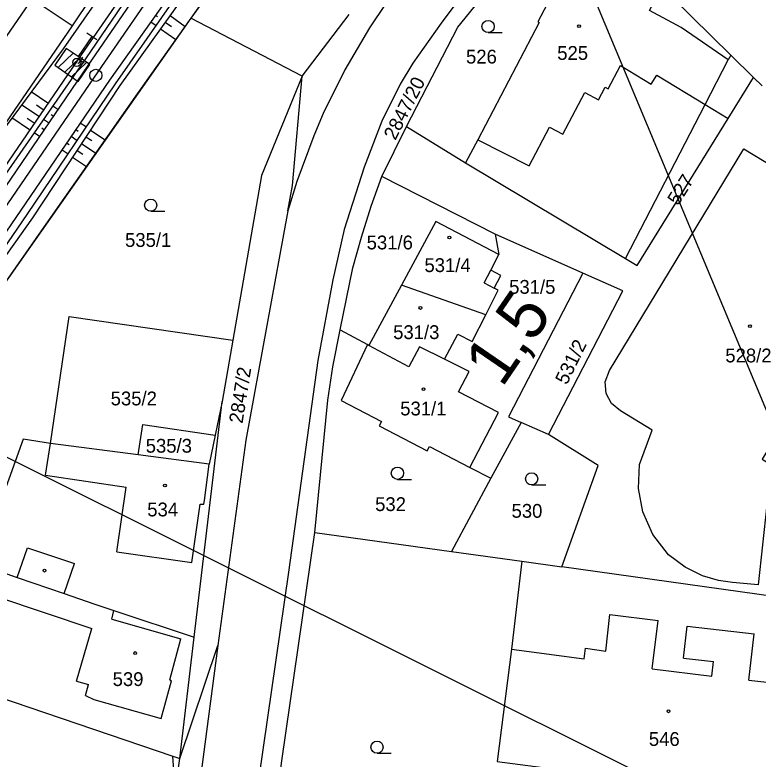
# Model space of a CAD drawing. Extents: x -558358 to -557517, y -1073786 to -1073189.
# Drawn here: x -558199.4 to -558108, y -1073559.5 to -1073467.9 of the extents above; entities that cross this region are included whole.
import ezdxf

# ---------------------------------------------------------------- set-up
doc = ezdxf.new("R2010")
doc.units = 0
for name, color, linetype in [('Hranice parcel', 7, 'Continuous'), ('Kolej', 7, 'Continuous'), ('Lomové body_krizky', 7, 'Continuous'), ('Návěst místo trati', 7, 'Continuous'), ('Parcelní čísla', 7, 'Continuous'), ('Plot - zábradlí', 7, 'Continuous'), ('Přejezd - štěrkové lože', 7, 'Continuous'), ('Sonda - šrafa - vrstevnice', 7, 'Continuous'), ('Svazek obcí údolí Desné', 7, 'Continuous'), ('Vnitřní kresba', 7, 'Continuous'), ('Vrstva 28', 7, 'Continuous'), ('Značky budov', 7, 'Continuous'), ('Značky kultur', 7, 'Continuous')]:
    doc.layers.add(name, color=color, linetype=linetype)

msp = doc.modelspace()

# ---------------------------------------------------------------- linework, layer by layer
at = {"layer": 'Hranice parcel'}
for p, q in [((-558111.36, -1073472.82), (-558131.54, -1073452.88)), ((-558192.36, -1073469.21), (-558197.28, -1073465.89)), ((-558164.08, -1073475.42), (-558177.75, -1073468.29)), ((-558164.08, -1073475.42), (-558158.31, -1073467.84)), ((-558108.55, -1073475.6), (-558111.36, -1073472.82)), ((-558111.65, -1073480.62), (-558108.55, -1073475.6)), ((-558108.55, -1073475.6), (-558107.49, -1073476.62)), ((-558154.26, -1073487.77), (-558151.25, -1073481.61)), ((-558151.25, -1073481.61), (-558143.96, -1073486.09)), ((-558143.96, -1073486.09), (-558124.31, -1073497.86)), ((-558140.32, -1073494.88), (-558154.26, -1073487.77)), ((-558164.73, -1073488.39), (-558165.84, -1073492.01)), ((-558140.32, -1073494.88), (-558139.88, -1073497.35)), ((-558129.53, -1073499.66), (-558140.32, -1073494.88)), ((-558151.86, -1073501.13), (-558155.87, -1073508.56)), ((-558141.49, -1073504.81), (-558151.86, -1073501.13)), ((-558159.39, -1073506.66), (-558156.05, -1073508.46)), ((-558172.6, -1073507.93), (-558173.92, -1073515.47)), ((-558155.87, -1073508.56), (-558156.05, -1073508.46)), ((-558177.37, -1073544.49), (-558173.92, -1073515.47)), ((-558173.92, -1073515.47), (-558174.76, -1073519.59)), ((-558137.14, -1073518.03), (-558140.85, -1073524.92)), ((-558133.75, -1073519.51), (-558137.14, -1073518.03)), ((-558184.24, -1073522.04), (-558195.03, -1073520.62)), ((-558143.44, -1073523.57), (-558140.85, -1073524.92)), ((-558140.85, -1073524.92), (-558145.69, -1073533.93)), ((-558162.5, -1073531.6), (-558145.69, -1073533.93)), ((-558145.69, -1073533.93), (-558137.04, -1073535.13)), ((-558137.04, -1073535.13), (-558132.14, -1073535.81)), ((-558102.24, -1073540.03), (-558132.14, -1073535.81)), ((-558179.14, -1073559.41), (-558177.37, -1073544.49)), ((-558179.14, -1073559.41), (-558174.43, -1073545.49)), ((-558174.43, -1073545.49), (-558176.44, -1073560.75)), ((-558210.55, -1073548.74), (-558179.99, -1073559.12)), ((-558181.3, -1073574.78), (-558179.14, -1073559.41)), ((-558179.99, -1073559.12), (-558179.14, -1073559.41))]:
    msp.add_line(p, q, dxfattribs=at)
for points in [[(-558086.19, -1073392.25), (-558100.56, -1073410.01), (-558117.51, -1073431.08), (-558131.78, -1073449.27), (-558138.48, -1073457.68), (-558143.38, -1073464.02), (-558146.99, -1073468.89), (-558150.46, -1073473.83), (-558152.02, -1073476.41), (-558154.26, -1073480.97), (-558156.46, -1073486.6), (-558158.91, -1073494.31), (-558160.3, -1073500.48), (-558162.16, -1073510.4), (-558165.76, -1073536.46), (-558169.94, -1073565.43), (-558173.74, -1073591.61), (-558177.66, -1073620.33), (-558178.51, -1073631.87), (-558179.02, -1073643), (-558179.24, -1073655.12), (-558179.45, -1073666.94), (-558179.49, -1073675.4)], [(-558129.07, -1073430.81), (-558128.89, -1073431.83), (-558128.89, -1073432.84), (-558129.1, -1073433.85), (-558129.56, -1073434.77), (-558130.67, -1073436.36), (-558148.52, -1073459.19), (-558153.8, -1073466.46), (-558155.8, -1073469.46), (-558158.84, -1073474.63), (-558161.5, -1073480.01), (-558162.64, -1073482.78), (-558164.73, -1073488.39)], [(-558151.25, -1073481.61), (-558144.94, -1073469.39), (-558131.54, -1073452.88)], [(-558111.36, -1073472.82), (-558111.67, -1073473.41), (-558117.43, -1073469.44), (-558121.34, -1073467.34), (-558121.11, -1073466.9), (-558126.57, -1073464.07), (-558126.8, -1073464.51), (-558131.6, -1073462.08), (-558135.08, -1073468.74), (-558134.91, -1073468.83), (-558142.45, -1073483.25), (-558143.96, -1073486.09)], [(-558235.03, -1073522.1), (-558231.61, -1073515.78), (-558197.28, -1073465.89)], [(-558164.08, -1073475.42), (-558169.06, -1073487.65), (-558172.6, -1073507.93)], [(-558165.84, -1073492.01), (-558165.27, -1073488.87), (-558164.08, -1073475.42)], [(-558124.31, -1073497.86), (-558114.5, -1073478.9), (-558111.65, -1073480.62)], [(-558124.31, -1073497.86), (-558122.86, -1073498.73), (-558111.65, -1073480.62)], [(-558091.42, -1073518.26), (-558101.25, -1073512.3), (-558107.5, -1073522.55), (-558106.36, -1073523.27), (-558107.97, -1073538.05), (-558111.12, -1073537.73), (-558112.87, -1073537.48), (-558114.81, -1073536.91), (-558116.94, -1073535.87), (-558118.99, -1073534.32), (-558120.94, -1073531.84), (-558122.18, -1073529.05), (-558122.71, -1073526.18), (-558122.56, -1073523.2), (-558121.01, -1073518.98), (-558124.91, -1073516.6), (-558126.01, -1073515.72), (-558126.67, -1073514.49), (-558126.79, -1073513.04), (-558126.28, -1073511.65), (-558109.74, -1073484.35), (-558090.14, -1073496.27), (-558093.41, -1073501.56), (-558085.97, -1073506.08)], [(-558159.39, -1073506.66), (-558157.84, -1073498.99), (-558156.78, -1073495.22), (-558155.58, -1073491.43), (-558154.26, -1073487.77)], [(-558165.84, -1073492.01), (-558171, -1073520.22), (-558174.43, -1073545.49)], [(-558139.88, -1073497.35), (-558147.64, -1073493.32), (-558151.86, -1073501.13)], [(-558141.49, -1073504.81), (-558139.95, -1073501.78), (-558140.44, -1073501.51), (-558139.64, -1073499.94), (-558140.88, -1073499.3), (-558139.88, -1073497.35)], [(-558129.53, -1073499.66), (-558138.67, -1073517.37), (-558137.14, -1073518.03)], [(-558133.75, -1073519.51), (-558124.62, -1073501.83), (-558129.53, -1073499.66)], [(-558195.03, -1073520.62), (-558192.73, -1073505.02), (-558172.6, -1073507.93)], [(-558146.56, -1073510.24), (-558144.94, -1073507.17), (-558143.16, -1073508.08), (-558141.49, -1073504.81)], [(-558162.5, -1073531.6), (-558160.9, -1073515.3), (-558160.3, -1073511.2), (-558159.39, -1073506.66)], [(-558156.05, -1073508.46), (-558159.29, -1073515.35), (-558154.32, -1073517.94), (-558154.58, -1073518.47), (-558148.69, -1073521.52), (-558148.41, -1073520.99), (-558143.44, -1073523.57)], [(-558146.56, -1073510.24), (-558149.62, -1073508.74), (-558150.95, -1073511.21), (-558155.87, -1073508.56)], [(-558143.44, -1073523.57), (-558139.9, -1073516.83), (-558144.85, -1073514.28), (-558143.52, -1073511.79), (-558146.56, -1073510.24)], [(-558184.24, -1073522.04), (-558183.68, -1073518.31), (-558174.76, -1073519.59)], [(-558174.76, -1073519.59), (-558175.5, -1073523.19), (-558184.24, -1073522.04)], [(-558132.14, -1073535.81), (-558127.68, -1073523.33), (-558133.75, -1073519.51)], [(-558195.03, -1073520.62), (-558198.39, -1073520.09), (-558203.93, -1073535.45)], [(-558169.56, -1073582.12), (-558166.59, -1073559.69), (-558162.5, -1073531.6)], [(-558203.93, -1073535.45), (-558199.11, -1073537.11), (-558193.35, -1073539.1), (-558189.69, -1073540.36), (-558187.24, -1073541.19), (-558177.37, -1073544.49)], [(-558137.04, -1073535.13), (-558138.34, -1073545.94), (-558140.1, -1073559.78), (-558127.81, -1073561.38), (-558128.13, -1073563.82), (-558128.85, -1073568.77)], [(-558181.3, -1073574.78), (-558179.75, -1073562.68), (-558179.99, -1073559.12)]]:
    msp.add_lwpolyline(points, dxfattribs=at)
at = {"layer": 'Kolej'}
msp.add_lwpolyline([(-558222.503, -1073523.521), (-558211.346, -1073507.264), (-558189.162, -1073474.891), (-558177.858, -1073458.424), (-558166.628, -1073442.093)], dxfattribs=at)
at = {"layer": 'Lomové body_krizky'}
for points in [[(-558160.273, -1073422.611), (-558170.916, -1073439.282), (-558182.072, -1073455.626), (-558193.455, -1073472.037), (-558204.951, -1073487.531), (-558215.829, -1073504.107), (-558218.74, -1073509.409), (-558221.469, -1073511.544)], [(-558158.606, -1073423.971), (-558169.145, -1073440.422), (-558180.255, -1073456.876), (-558191.265, -1073472.78), (-558202.458, -1073489.109), (-558213.804, -1073505.706), (-558218.063, -1073510.897), (-558220.015, -1073511.365), (-558220.657, -1073512.063)], [(-558152.696, -1073428.173), (-558163.486, -1073444.26), (-558174.921, -1073460.397), (-558186.509, -1073476.578), (-558197.243, -1073492.857), (-558208.765, -1073509.054), (-558219.853, -1073525.269), (-558227.104, -1073535.745), (-558230.394, -1073540.522), (-558231.004, -1073543.032)]]:
    msp.add_lwpolyline(points, dxfattribs=at)
at = {"layer": 'Návěst místo trati'}
for p, q in [((-558189.326, -1073470.959), (-558190.562, -1073470.111)), ((-558192.26, -1073472.584), (-558194.087, -1073474.362)), ((-558193.263, -1073474.928), (-558191.436, -1073473.15)), ((-558191.73, -1073473.195), (-558190.906, -1073473.761)), ((-558191.601, -1073473.89), (-558191.035, -1073473.066)), ((-558190.611, -1073473.716), (-558192.438, -1073475.494)), ((-558191.831, -1073473.723), (-558191.731, -1073473.723)), ((-558191.831, -1073473.723), (-558191.731, -1073473.723))]:
    msp.add_line(p, q, dxfattribs=at)
msp.add_lwpolyline([(-558189.944, -1073470.535), (-558191.642, -1073473.008), (-558193.085, -1073472.018), (-558194.499, -1073474.079), (-558191.614, -1073476.06), (-558190.199, -1073473.999), (-558191.642, -1073473.008)], dxfattribs=at)
for centre, radius in [((-558191.781, -1073473.723), 0.5), ((-558191.781, -1073473.723), 0.5), ((-558189.454, -1073475.317), 0.75)]:
    msp.add_circle(centre, radius, dxfattribs=at)
at = {"layer": 'Plot - zábradlí'}
msp.add_lwpolyline([(-558226.6, -1073552.392), (-558229.624, -1073542.122), (-558228.842, -1073541.337), (-558220.937, -1073529.813), (-558210.663, -1073515.209), (-558195.563, -1073493.62), (-558184.312, -1073477.574), (-558177.726, -1073468.266), (-558161.671, -1073445.553), (-558150.682, -1073429.948)], dxfattribs=at)
at = {"layer": 'Přejezd - štěrkové lože'}
for p, q in [((-558182.699, -1073468.723), (-558182.045, -1073469.186)), ((-558182.12, -1073467.907), (-558181.861, -1073468.091)), ((-558194.146, -1073479.528), (-558194.747, -1073479.118)), ((-558194.709, -1073480.354), (-558194.953, -1073480.188)), ((-558195.273, -1073481.18), (-558195.892, -1073480.758)), ((-558191.364, -1073481.16), (-558190.622, -1073481.665)), ((-558196.4, -1073482.833), (-558197.036, -1073482.399)), ((-558195.836, -1073482.007), (-558196.087, -1073481.835)), ((-558191.927, -1073481.987), (-558191.629, -1073482.19)), ((-558192.489, -1073482.814), (-558191.74, -1073483.323)), ((-558193.052, -1073483.64), (-558192.751, -1073483.845)), ((-558193.614, -1073484.467), (-558192.858, -1073484.981))]:
    msp.add_line(p, q, dxfattribs=at)
for points in [[(-558233.117, -1073536.268), (-558231.44, -1073532.587), (-558224.313, -1073522.106), (-558213.317, -1073506.016), (-558201.976, -1073489.477), (-558190.684, -1073473.296), (-558179.755, -1073457.161), (-558168.654, -1073440.763), (-558157.793, -1073424.718)], [(-558157.055, -1073425.159), (-558168.025, -1073441.175), (-558179.14, -1073457.549), (-558190.456, -1073474.118), (-558201.291, -1073490.004), (-558212.692, -1073506.364), (-558223.924, -1073522.502), (-558230.654, -1073533.02), (-558233.117, -1073536.268)], [(-558154.327, -1073427.065), (-558164.836, -1073443.279), (-558176.229, -1073459.594), (-558187.787, -1073475.903), (-558198.666, -1073491.892), (-558209.907, -1073508.326), (-558221.193, -1073524.358), (-558228.269, -1073534.998), (-558231.505, -1073539.539)], [(-558231.505, -1073539.539), (-558230.175, -1073538.965), (-558227.649, -1073535.494), (-558220.305, -1073524.952), (-558209.15, -1073508.866), (-558197.896, -1073492.456), (-558187.035, -1073476.342), (-558175.627, -1073459.983), (-558164.25, -1073443.72), (-558153.522, -1073427.772)]]:
    msp.add_lwpolyline(points, dxfattribs=at)
at = {"layer": 'Sonda - šrafa - vrstevnice'}
for p, q in [((-558180.327, -1073467.945), (-558178.45, -1073469.289)), ((-558181.491, -1073469.572), (-558179.605, -1073470.922)), ((-558180.909, -1073468.759), (-558180.157, -1073469.298)), ((-558195.352, -1073478.742), (-558197.392, -1073477.343)), ((-558196.482, -1073480.391), (-558198.584, -1073478.95)), ((-558195.917, -1073479.567), (-558196.746, -1073478.999)), ((-558197.613, -1073482.041), (-558199.777, -1073480.558)), ((-558197.048, -1073481.216), (-558197.901, -1073480.631)), ((-558190.113, -1073482.044), (-558188.29, -1073483.247)), ((-558190.664, -1073482.879), (-558189.944, -1073483.354)), ((-558191.214, -1073483.714), (-558189.438, -1073484.885)), ((-558191.765, -1073484.548), (-558191.064, -1073485.011)), ((-558192.315, -1073485.383), (-558190.587, -1073486.523))]:
    msp.add_line(p, q, dxfattribs=at)
at = {"layer": 'Svazek obcí údolí Desné'}
for p, q in [((-558138.47, -1073412.32), (-558177.75, -1073468.29)), ((-558157.08, -1073415.91), (-558192.36, -1073469.21)), ((-558177.75, -1073468.29), (-558220.99, -1073529.81)), ((-558192.36, -1073469.21), (-558234.96, -1073531.36))]:
    msp.add_line(p, q, dxfattribs=at)
at = {"layer": 'Vnitřní kresba'}
for p, q in [((-558126.45, -1073476.96), (-558124.93, -1073474.1)), ((-558124.93, -1073474.1), (-558121.12, -1073476.4)), ((-558114.5, -1073478.9), (-558111.67, -1073473.41)), ((-558121.12, -1073476.4), (-558120.46, -1073475.31)), ((-558120.46, -1073475.31), (-558114.5, -1073478.9)), ((-558127.63, -1073478.35), (-558126.79, -1073476.79)), ((-558126.79, -1073476.79), (-558126.45, -1073476.96)), ((-558132, -1073482.54), (-558129.3, -1073477.44)), ((-558129.3, -1073477.44), (-558127.63, -1073478.35)), ((-558136.15, -1073486.45), (-558133.63, -1073481.7)), ((-558133.63, -1073481.7), (-558132, -1073482.54)), ((-558142.45, -1073483.25), (-558136.15, -1073486.45)), ((-558141.68, -1073500.85), (-558140.88, -1073499.3)), ((-558141.68, -1073500.85), (-558140.44, -1073501.51)), ((-558195.64, -1073524.53), (-558195.03, -1073520.62)), ((-558176.08, -1073527.66), (-558175.5, -1073523.19)), ((-558195.64, -1073524.53), (-558185.73, -1073525.99)), ((-558186.85, -1073533.98), (-558185.73, -1073525.99)), ((-558177.65, -1073535.29), (-558176.63, -1073528.09)), ((-558176.63, -1073528.09), (-558176.18, -1073528.11)), ((-558176.18, -1073528.11), (-558176.08, -1073527.66)), ((-558199.11, -1073537.11), (-558197.85, -1073533.46)), ((-558197.85, -1073533.46), (-558192.08, -1073535.4)), ((-558186.85, -1073533.98), (-558177.65, -1073535.29)), ((-558193.35, -1073539.1), (-558192.08, -1073535.4)), ((-558205.25, -1073538.29), (-558189.93, -1073543.4)), ((-558187.49, -1073542.24), (-558187.24, -1073541.19)), ((-558126.72, -1073546.2), (-558126.22, -1073541.7)), ((-558126.22, -1073541.7), (-558120.27, -1073542.43)), ((-558187.49, -1073542.24), (-558179, -1073544.67)), ((-558121, -1073548.38), (-558120.27, -1073542.43)), ((-558191.85, -1073549.89), (-558189.93, -1073543.4)), ((-558117.17, -1073547.04), (-558116.72, -1073543.11)), ((-558116.72, -1073543.11), (-558108.48, -1073544.08)), ((-558180.35, -1073549.71), (-558179, -1073544.67)), ((-558109.12, -1073549.75), (-558108.48, -1073544.08)), ((-558138.34, -1073545.94), (-558129.39, -1073547.14)), ((-558129.39, -1073547.14), (-558129.22, -1073545.83)), ((-558129.22, -1073545.83), (-558126.72, -1073546.2)), ((-558117.17, -1073547.04), (-558113.48, -1073547.47)), ((-558113.69, -1073549.26), (-558113.48, -1073547.47)), ((-558121, -1073548.38), (-558113.69, -1073549.26)), ((-558191.85, -1073549.89), (-558190.36, -1073550.31)), ((-558181.43, -1073554.48), (-558180.14, -1073549.84)), ((-558180.35, -1073549.71), (-558180.14, -1073549.84)), ((-558109.12, -1073549.75), (-558102.5, -1073550.54)), ((-558190.71, -1073551.65), (-558190.36, -1073550.31)), ((-558190.71, -1073551.65), (-558189.68, -1073552.16)), ((-558189.68, -1073552.16), (-558181.43, -1073554.48))]:
    msp.add_line(p, q, dxfattribs=at)
at = {"layer": 'Vrstva 28'}
for p, q in [((-558150.161, -1073413.052), (-558044.903, -1073665.427)), ((-558220.138, -1073512.456), (-557941.756, -1073651.484))]:
    msp.add_line(p, q, dxfattribs=at)
at = {"layer": 'Značky budov'}
for centre in [(-558130.007, -1073469.269), (-558145.967, -1073495.269), (-558149.527, -1073503.949), (-558108.987, -1073506.199), (-558149.147, -1073513.949), (-558180.947, -1073525.799), (-558195.767, -1073536.279), (-558184.617, -1073546.429), (-558119.017, -1073553.599)]:
    msp.add_circle(centre, 0.175, dxfattribs=at)
at = {"layer": 'Značky kultur'}
for p, q in [((-558141.203, -1073470.05), (-558139.453, -1073470.05)), ((-558182.703, -1073492.04), (-558180.953, -1073492.04)), ((-558152.353, -1073525.05), (-558150.603, -1073525.05)), ((-558135.843, -1073525.74), (-558134.093, -1073525.74)), ((-558154.863, -1073558.76), (-558153.113, -1073558.76))]:
    msp.add_line(p, q, dxfattribs=at)
for centre in [(-558141.203, -1073469.3), (-558182.703, -1073491.29), (-558152.353, -1073524.3), (-558135.843, -1073524.99), (-558154.863, -1073558.01)]:
    msp.add_circle(centre, 0.75, dxfattribs=at)

# ---------------------------------------------------------------- texts
at = {"layer": 'Návěst místo trati'}
msp.add_text('1,5', height=6, rotation=55.56261, dxfattribs=at).set_placement((-558139.506, -1073513.877))
at = {"layer": 'Parcelní čísla'}
for s, p in [('526', (-558143.915, -1073473.86)), ('525', (-558132.695, -1073473.41)), ('535/1', (-558185.858, -1073496.43)), ('531/6', (-558156.138, -1073496.739)), ('531/4', (-558149.028, -1073499.529)), ('531/5', (-558138.61, -1073502.207)), ('531/3', (-558152.878, -1073507.779)), ('528/2', (-558112.018, -1073510.65)), ('535/2', (-558187.628, -1073515.94)), ('531/1', (-558152.01, -1073517.181)), ('535/3', (-558183.318, -1073521.763)), ('532', (-558155.095, -1073528.95)), ('534', (-558183.129, -1073529.605)), ('530', (-558138.315, -1073529.779)), ('539', (-558187.385, -1073550.489)), ('546', (-558121.425, -1073557.86))]:
    msp.add_text(s, height=1.7, dxfattribs=at).set_placement(p)
for s, rotation, p in [('2847/20', 63, (-558152.615, -1073483.402)), ('527', 58, (-558117.821, -1073491.432)), ('531/2', 64, (-558131.512, -1073513.497)), ('2847/2', 81, (-558171.409, -1073518.235))]:
    msp.add_text(s, height=1.7, rotation=rotation, dxfattribs=at).set_placement(p)

doc.saveas('drawing.dxf')
